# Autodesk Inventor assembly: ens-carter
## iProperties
Author: robert
Shininess: 41.0
Angle Display Precision: 2
Document Length Units: 11269
Document Angle Units: 11283
Document Time Units: 11279
Document Mass Units: 11290
Document Length Units Precision: 3
Document Angle Units Precision: 2
Compacted: True
PropertySet Name: _Private Model Information
Created: 2002-09
Part Number: ens-carter
Document SubType Name: Assemblage
Designer: robert
Control State: 0
Master: False
Checked Out: False
PropertySet Name: Design Tracking Control
Density: 0.0
Volumn: 0.0
Area: 0.0
PropertySet Name: Model Information
